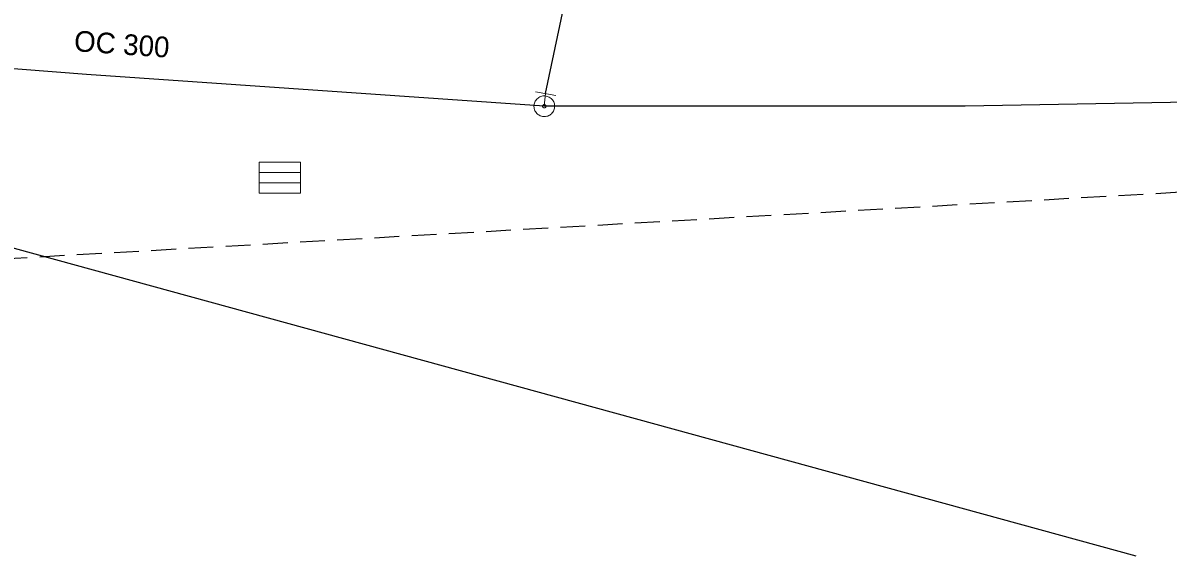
# Model space of a CAD drawing. Extents: x -725643 to -725418, y -978375 to -978221.
# Drawn here: x -725502 to -725446.7, y -978366.6 to -978340.9 of the extents above; entities that cross this region are included whole.
import ezdxf

# ---------------------------------------------------------------- set-up
doc = ezdxf.new("R2010")
doc.units = 0
doc.header["$LTSCALE"] = 0.4
doc.linetypes.add('MEDIUM_DASHED', pattern=[4.5, 3, -1.5])
doc.layers.add('1', color=7, linetype='Continuous')
for name, color, linetype, lineweight in [('14', 7, 'Continuous', 25), ('17', 7, 'Continuous', 25), ('22', 7, 'Continuous', 13), ('34', 7, 'Continuous', 13), ('47', 7, 'Continuous', 13), ('63', 7, 'MEDIUM_DASHED', 25)]:
    doc.layers.add(name, color=color, linetype=linetype, lineweight=lineweight)

msp = doc.modelspace()

# ---------------------------------------------------------------- linework, layer by layer
at = {"layer": '14', "lineweight": 13}
msp.add_line((-725476.788, -978344.909), (-725476.724, -978344.299), dxfattribs=at)
at = {"layer": '14'}
msp.add_line((-725448.203, -978366.647), (-725503.472, -978351.493), dxfattribs=at)
at = {"layer": '17'}
for points in [[(-725476.724, -978344.299), (-725473.829, -978330.592), (-725473.78, -978330.284), (-725473.397, -978330.332)], [(-725476.788, -978344.909), (-725498.899, -978343.37), (-725515.094, -978342.114), (-725516.432, -978342.059)], [(-725429.657, -978344.382), (-725432.239, -978344.44), (-725442.02, -978344.64), (-725456.449, -978344.899), (-725476.788, -978344.909)]]:
    msp.add_lwpolyline(points, dxfattribs=at)
at = {"layer": '22'}
for p, q in [((-725490.559, -978348.113), (-725488.559, -978348.113)), ((-725490.559, -978348.613), (-725488.559, -978348.613))]:
    msp.add_line(p, q, dxfattribs=at)
msp.add_lwpolyline([(-725490.559, -978347.613), (-725488.559, -978347.613), (-725488.559, -978349.113), (-725490.559, -978349.113)], close=True, dxfattribs=at)
at = {"layer": '34'}
msp.add_line((-725477.215, -978344.205), (-725476.233, -978344.393), dxfattribs=at)
at = {"layer": '47'}
for points in [[(-725476.595, -978344.447), (-725476.644, -978344.43), (-725476.695, -978344.417), (-725476.747, -978344.411), (-725476.799, -978344.409), (-725476.851, -978344.413), (-725476.903, -978344.422), (-725476.953, -978344.437), (-725477.001, -978344.457), (-725477.047, -978344.482), (-725477.091, -978344.511), (-725477.131, -978344.545), (-725477.167, -978344.583), (-725477.199, -978344.624), (-725477.226, -978344.669), (-725477.249, -978344.716), (-725477.266, -978344.765), (-725477.279, -978344.816), (-725477.286, -978344.869), (-725477.287, -978344.92), (-725477.283, -978344.972), (-725477.274, -978345.024), (-725477.259, -978345.075), (-725477.239, -978345.123), (-725477.215, -978345.169), (-725477.185, -978345.212), (-725477.151, -978345.252), (-725477.113, -978345.288), (-725477.072, -978345.32), (-725477.027, -978345.347), (-725476.98, -978345.37), (-725476.931, -978345.387), (-725476.88, -978345.4), (-725476.828, -978345.407), (-725476.776, -978345.408), (-725476.724, -978345.404), (-725476.672, -978345.395), (-725476.622, -978345.381), (-725476.573, -978345.361), (-725476.527, -978345.336), (-725476.484, -978345.306), (-725476.444, -978345.272), (-725476.408, -978345.235), (-725476.376, -978345.193), (-725476.349, -978345.148), (-725476.326, -978345.101), (-725476.309, -978345.052), (-725476.296, -978345.001), (-725476.289, -978344.95), (-725476.288, -978344.897), (-725476.292, -978344.845), (-725476.301, -978344.793), (-725476.316, -978344.744), (-725476.335, -978344.695), (-725476.361, -978344.649), (-725476.39, -978344.605), (-725476.424, -978344.565), (-725476.462, -978344.53), (-725476.503, -978344.497), (-725476.548, -978344.47)], [(-725476.756, -978344.833), (-725476.764, -978344.829), (-725476.772, -978344.828), (-725476.781, -978344.827), (-725476.789, -978344.827), (-725476.798, -978344.827), (-725476.806, -978344.829), (-725476.815, -978344.831), (-725476.823, -978344.834), (-725476.83, -978344.839), (-725476.837, -978344.843), (-725476.844, -978344.849), (-725476.85, -978344.855), (-725476.855, -978344.862), (-725476.86, -978344.869), (-725476.863, -978344.877), (-725476.867, -978344.885), (-725476.868, -978344.893), (-725476.869, -978344.902), (-725476.869, -978344.91), (-725476.869, -978344.919), (-725476.867, -978344.927), (-725476.865, -978344.936), (-725476.862, -978344.944), (-725476.858, -978344.952), (-725476.853, -978344.958), (-725476.847, -978344.965), (-725476.841, -978344.971), (-725476.834, -978344.976), (-725476.827, -978344.981), (-725476.819, -978344.984), (-725476.811, -978344.988), (-725476.803, -978344.989), (-725476.794, -978344.99), (-725476.786, -978344.99), (-725476.777, -978344.99), (-725476.769, -978344.989), (-725476.76, -978344.986), (-725476.752, -978344.983), (-725476.744, -978344.979), (-725476.738, -978344.974), (-725476.731, -978344.968), (-725476.725, -978344.962), (-725476.72, -978344.955), (-725476.715, -978344.948), (-725476.712, -978344.94), (-725476.708, -978344.932), (-725476.707, -978344.924), (-725476.706, -978344.915), (-725476.706, -978344.907), (-725476.706, -978344.898), (-725476.707, -978344.89), (-725476.71, -978344.881), (-725476.713, -978344.873), (-725476.718, -978344.866), (-725476.722, -978344.859), (-725476.728, -978344.852), (-725476.734, -978344.846), (-725476.741, -978344.841), (-725476.748, -978344.836)]]:
    msp.add_lwpolyline(points, close=True, dxfattribs=at)
at = {"layer": '63'}
msp.add_lwpolyline([(-725504.582, -978332.573), (-725495.092, -978321.408), (-725495.092, -978321.408), (-725457.131, -978324.199), (-725457.131, -978324.199), (-725456.573, -978271.166), (-725456.573, -978271.166), (-725442.617, -978268.933), (-725442.617, -978268.933), (-725440.663, -978348.762), (-725440.663, -978348.762), (-725504.582, -978352.39)], dxfattribs=at)

# ---------------------------------------------------------------- texts
at = {"layer": '1'}
msp.add_text('OC 300', height=1, rotation=356, dxfattribs=at).set_placement((-725499.529, -978342.244))

doc.saveas('drawing.dxf')
